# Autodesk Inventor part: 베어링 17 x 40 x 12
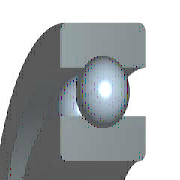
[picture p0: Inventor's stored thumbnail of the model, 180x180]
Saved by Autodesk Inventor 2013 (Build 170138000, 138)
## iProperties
IsCustomPart: 1
Created: 2012-02
Part Number: 베어링 17 x 40 x 12
Material: 강철, 연강
Description: 깊은 그루브 볼 베어링
Document SubType Name: Modeling
Standard: KS B 2023
Designer: mduedu
Standards Organization: KS
Language: ko-KR
Size Designation: 6203 - 17 x 40 x 12
Categories: <MemberInstance><Categories><Category DisplayName="샤프트 부품" InternalName="7f7aeb1f-a693-4053-b835-cee3144e0d98" Mnemonic="SHFT"><Category DisplayName="베어링" Inter
Density: 7.86 g/cm^3
Mass: 64.9809 g
Surface Area: 64.3582 cm^2
Volume: 8.26729 cm^3
Author: mduedu
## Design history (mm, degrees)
sketch "스케치" dims "d0" = 5.98 (= -0.26 x WD + 0.26 x BD)
  geometry: L1 (3.01, 14.25)-(8.99, 14.25); L2 (6, 14.25)-(6, 11.26); L3 (6, 14.25)-(6, 17.24); L4 (3.778, 12.249)-(0, 12.249); L5 (0, 8.5)-(12, 8.5); L6 (3.778, 16.251)-(0, 16.251); L7 (0, 20)-(12, 20); L8 (12, 8.5)-(12, 12.249); L9 (8.222, 12.249)-(12, 12.249); L10 (8.222, 16.251)-(12, 16.251); L11 (12, 20)-(12, 16.251); L12 (-1.4, 0)-(8.4, 0) reference; L13 (0, -0.3)-(0, 5.3) reference
  constraints: 22 end point, 4 point on line, 2 collinear, 2 perpendicular, 2 symmetric about line, 1 midpoint, 1 parallel, 14 other
  dimensions: "d9" = 17 diameter of L5 L12 (= WD); "d11" = 40 diameter of L7 L12 (= BD); "d12" = 12 distance between parallel lines of L8 L13 (= KB); "d13" = 24.498 diameter of L9 L12 (= 0.326 x BD + 0.674 x WD)
revolve "본체" stored, may be unused: angle "d6" = 90 deg
revolve "볼" stored, may be unused: angle "d7" = 90 deg
pattern_circular "IDS_ARRAYBALL[SIMPL:T]" dims angle "d3" = 360 deg
body "Solid1"
fillet "모깎기1" dims "d1" = 0.6 (= KRS)
other parameters: "WD" = 17 [user parameter; used in 5 equation terms], "BD" = 40 [user parameter; used in 5 equation terms], "KB" = 12 [user parameter; used in 1 equation term], "KRS" = 0.6 [user parameter; used in 1 equation term], "d4" = 0, "d5" = 0, "d8" = 0, "d14" = 0, "d15" = 0, "BBA" = 0 [user parameter], "BC0" = 4750000 [user parameter], "BC" = 9560000 [user parameter], "WR" = 8.5 (= 0.5 x WD) [user parameter]
